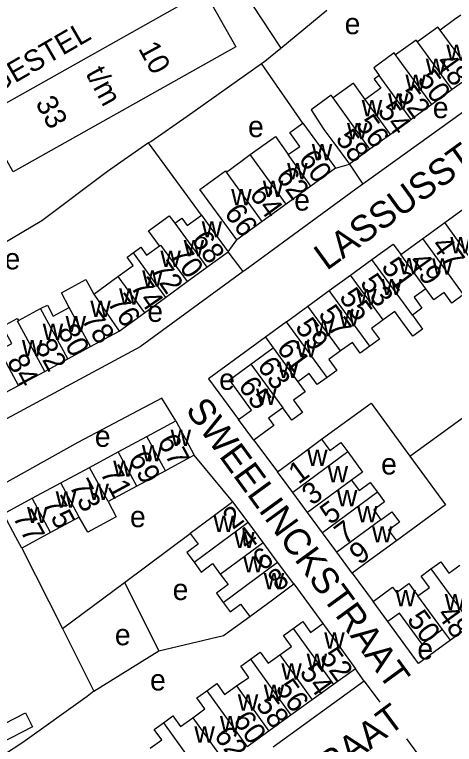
# Model space of a CAD drawing. Extents: x 159045 to 160918, y 380454 to 382516.
# Drawn here: x 159907.1 to 159990.1, y 381294.6 to 381432.4 of the extents above; entities that cross this region are included whole.
import ezdxf

# ---------------------------------------------------------------- set-up
doc = ezdxf.new("R2010")
doc.units = 0
for name, color, linetype in [('BLT_Basislijn', 7, 'Continuous'), ('BLT_Bebouwing', 7, 'Continuous'), ('BLT_Centroide', 7, 'Continuous'), ('BLT_Huisnummer', 7, 'Continuous'), ('BLT_Huisnummer_ tussenligend', 7, 'Continuous'), ('BLT_Huisnummer_zonder_bebouwing', 7, 'Continuous'), ('BLT_Onderverdeling_panden', 7, 'Continuous'), ('BLT_Plantopo', 7, 'Continuous'), ('BLT_Straatnaam', 7, 'Continuous'), ('BLT_Straatnaam_verkleind', 7, 'Continuous')]:
    doc.layers.add(name, color=color, linetype=linetype)

msp = doc.modelspace()

# ---------------------------------------------------------------- linework, layer by layer
at = {"layer": 'BLT_Basislijn'}
for p, q in [((159957.35, 381426.13), (159966.05, 381433.28)), ((159939.67, 381413.24), (159953.68, 381423.18)), ((159961.5, 381411.96), (159953.68, 381423.18)), ((160004.68, 381423.38), (159972.84, 381400.42)), ((159942.37, 381394.57), (159932.38, 381408.21)), ((159967.69, 381403.45), (159970.28, 381404.18)), ((159970.28, 381404.18), (159972.84, 381400.42)), ((159947.41, 381387.65), (159949.03, 381389.88)), ((159950.25, 381383.9), (159947.41, 381387.65)), ((159981.71, 381349.05), (160016.01, 381374.12)), ((159937.49, 381355.7), (159934.9, 381360.03)), ((159952.22, 381352.05), (159956.71, 381346.11)), ((159948.31, 381340.43), (159940.98, 381349.22)), ((159927.82, 381325.22), (159940.24, 381334.46)), ((159908.46, 381331.7), (159916.1, 381316.49)), ((159970.82, 381326.94), (159974.76, 381321.6)), ((159916.1, 381316.49), (159927.82, 381325.22)), ((159927.82, 381325.22), (159934.31, 381312.3)), ((159959.78, 381324.93), (159965.25, 381317.43)), ((159916.1, 381316.49), (159922.02, 381304.7)), ((159922.02, 381304.7), (159934.31, 381312.3)), ((159973.08, 381306.59), (159971.41, 381308.89)), ((159973.08, 381306.59), (159976.06, 381302.58)), ((159981.09, 381295.66), (159984.02, 381291.61))]:
    msp.add_line(p, q, dxfattribs=at)
for points in [[(159934.28, 381462.49), (159944.7, 381445.38), (159955.5, 381428.86), (159957.35, 381426.13)], [(159953.68, 381423.18), (159954.31, 381423.63), (159957.35, 381426.13)], [(159932.38, 381408.21), (159932.8, 381408.48), (159939.67, 381413.24)], [(159932.38, 381408.21), (159924.6, 381402.83), (159912.24, 381393.51), (159886.48, 381378.25)], [(159972.84, 381400.42), (159971.51, 381399.46), (159950.54, 381384.11), (159950.25, 381383.9)], [(159950.25, 381383.9), (159930.77, 381369.73), (159899.79, 381353.03)], [(159954.43, 381371.54), (159943.71, 381363.68), (159949.36, 381355.98)], [(159934.9, 381360.03), (159919.03, 381351.63), (159902.43, 381342.39), (159903.09, 381341.29)], [(159965.04, 381352.24), (159974.39, 381359.07), (159981.71, 381349.05)], [(159981.71, 381349.05), (159988.42, 381339.87), (159979.15, 381333.07)], [(159934.31, 381312.3), (159946.53, 381315.18), (159951.47, 381318.77)], [(159989.36, 381314.28), (159983.36, 381309.88), (159977.55, 381317.81)], [(159973.08, 381306.59), (159955.92, 381294.07)], [(159922.02, 381304.7), (159920.78, 381303.64), (159908.65, 381294.99), (159905.36, 381292.86)]]:
    msp.add_lwpolyline(points, dxfattribs=at)
at = {"layer": 'BLT_Bebouwing'}
for p, q in [((159993.59, 381421.11), (159989.7, 381418.29)), ((159989.7, 381418.29), (159985.82, 381415.46)), ((159985.82, 381415.46), (159981.93, 381412.64)), ((159981.93, 381412.64), (159978.05, 381409.82)), ((159978.05, 381409.82), (159974.16, 381407)), ((159974.16, 381407), (159970.28, 381404.18)), ((159967.69, 381403.45), (159963.02, 381400.06)), ((159963.02, 381400.06), (159958.36, 381396.67)), ((159958.36, 381396.67), (159953.85, 381393.39)), ((159988.29, 381393.15), (159992.03, 381395.88)), ((159953.85, 381393.39), (159949.03, 381389.88)), ((159984.15, 381390.14), (159988.29, 381393.15)), ((159979.99, 381387.11), (159984.15, 381390.14)), ((159943.39, 381384.72), (159947.41, 381387.65)), ((159970.5, 381383.25), (159974.52, 381386.18)), ((159939.66, 381382.01), (159943.39, 381384.72)), ((159922.04, 381379.64), (159926.6, 381382.96)), ((159966.49, 381380.33), (159970.5, 381383.25)), ((159935.58, 381379.03), (159939.66, 381382.01)), ((159962.45, 381377.38), (159966.49, 381380.33)), ((159931.58, 381376.12), (159935.58, 381379.03)), ((159958.39, 381374.42), (159962.45, 381377.38)), ((159907.79, 381374.65), (159911.99, 381376.92)), ((159926.83, 381372.66), (159931.58, 381376.12)), ((159921.42, 381369.74), (159926.83, 381372.66)), ((159917.12, 381367.42), (159921.42, 381369.74)), ((159951.69, 381366.4), (159955.92, 381369.49)), ((159912.78, 381365.07), (159917.12, 381367.42)), ((159947.64, 381363.46), (159951.69, 381366.4)), ((159907.79, 381362.37), (159912.78, 381365.07)), ((159902.82, 381359.69), (159907.79, 381362.37)), ((159932.07, 381352.78), (159937.49, 381355.7)), ((159937.49, 381355.7), (159940.98, 381349.22)), ((159926.65, 381349.86), (159932.07, 381352.78)), ((159921.23, 381346.94), (159926.65, 381349.86)), ((159915.81, 381344.02), (159921.23, 381346.94)), ((159935.56, 381346.3), (159930.14, 381343.38)), ((159959.59, 381342.19), (159956.71, 381346.11)), ((159910.39, 381341.1), (159915.81, 381344.02)), ((159930.14, 381343.38), (159924.72, 381340.46)), ((159962.38, 381338.41), (159959.59, 381342.19)), ((159904.96, 381338.18), (159910.39, 381341.1)), ((159951.16, 381336.57), (159948.31, 381340.43)), ((159919.3, 381337.54), (159913.88, 381334.62)), ((159965.18, 381334.6), (159962.38, 381338.41)), ((159953.98, 381332.76), (159951.16, 381336.57)), ((159913.88, 381334.62), (159908.46, 381331.7)), ((159967.89, 381330.91), (159965.18, 381334.6)), ((159956.74, 381329.04), (159953.98, 381332.76)), ((159970.82, 381326.94), (159967.89, 381330.91)), ((159959.78, 381324.93), (159956.74, 381329.04)), ((159974.76, 381321.6), (159978.45, 381324.29)), ((159977.55, 381317.81), (159974.76, 381321.6)), ((159967.29, 381305.92), (159963.27, 381303.02)), ((159963.27, 381303.02), (159959.25, 381300.11)), ((159959.25, 381300.11), (159955.08, 381297.1)), ((159955.08, 381297.1), (159951, 381294.16))]:
    msp.add_line(p, q, dxfattribs=at)
for points in [[(159991.35, 381432.36), (159990.15, 381431.49), (159987.42, 381429.51)], [(159987.42, 381429.51), (159986.99, 381430.09), (159983.13, 381427.29)], [(159983.13, 381427.29), (159982.88, 381427.63), (159979.01, 381424.82)], [(159979.01, 381424.82), (159978.73, 381425.21), (159974.87, 381422.4), (159975.89, 381420.96)], [(159975.89, 381420.96), (159974.96, 381420.28), (159976.23, 381418.54), (159973.27, 381416.4)], [(159973.27, 381416.4), (159971.08, 381419.5), (159967.21, 381416.7)], [(159967.21, 381416.7), (159966.84, 381417.2), (159963.06, 381414.46), (159965.49, 381410.77), (159967.34, 381408.23), (159970.28, 381404.18)], [(159958.7, 381406.01), (159960.93, 381407.52), (159959.02, 381410.16), (159961.5, 381411.96)], [(159961.5, 381411.96), (159964.75, 381407.5), (159967.69, 381403.45)], [(159951.58, 381406), (159956.31, 381409.44), (159958.7, 381406.01)], [(159947.07, 381402.71), (159951.58, 381406)], [(159949.03, 381389.88), (159946.09, 381393.92), (159942.08, 381399.43), (159946.9, 381402.94), (159947.07, 381402.71)], [(159934.45, 381388.79), (159932.39, 381391.62), (159936.29, 381394.46), (159937.33, 381393.03)], [(159937.33, 381393.03), (159938.64, 381393.98), (159939.65, 381392.59), (159942.37, 381394.57)], [(159942.37, 381394.57), (159944.47, 381391.7), (159947.41, 381387.65)], [(159929.44, 381387.45), (159930.9, 381388.51), (159932, 381387), (159934.45, 381388.79)], [(159974.52, 381386.18), (159978.54, 381389.1), (159979.99, 381387.11)], [(159926.6, 381382.96), (159929.49, 381385.06), (159928.33, 381386.64), (159929.44, 381387.45)], [(159917.41, 381377.15), (159915.92, 381379.91), (159920.54, 381382.4), (159922.04, 381379.64)], [(159984.69, 381380.65), (159982.51, 381379.06), (159983.99, 381377.03), (159982.17, 381375.7)], [(159991.85, 381379.56), (159989.64, 381377.96), (159988.17, 381379.98), (159986.22, 381378.56), (159984.69, 381380.65)], [(159911.99, 381376.92), (159913.27, 381377.6), (159914.39, 381375.52), (159917.41, 381377.15)], [(159982.17, 381375.7), (159984.1, 381373.04), (159982.28, 381371.71), (159980.34, 381374.36), (159978.87, 381376.39), (159976.67, 381374.79)], [(159904.16, 381369.08), (159906.53, 381370.36), (159904.81, 381373.54), (159907.58, 381375.04), (159907.79, 381374.65)], [(159976.67, 381374.79), (159974.47, 381373.19), (159975.96, 381371.15), (159974.15, 381369.83)], [(159958.39, 381374.42), (159954.43, 381371.54)], [(159954.43, 381371.54), (159955.92, 381369.49)], [(159974.15, 381369.83), (159972.33, 381368.5), (159970.85, 381370.54), (159968.62, 381368.92)], [(159968.62, 381368.92), (159966.39, 381367.29), (159967.89, 381365.23), (159966.06, 381363.9)], [(159966.06, 381363.9), (159964.23, 381362.56), (159962.7, 381364.67), (159960.57, 381363.11)], [(159949.36, 381355.98), (159951.8, 381357.76), (159947.64, 381363.46)], [(159960.57, 381363.11), (159961.94, 381361.22), (159959.74, 381359.62), (159961.43, 381357.31), (159959.39, 381355.83), (159957.7, 381358.15)], [(159957.7, 381358.15), (159955.02, 381356.2), (159956.02, 381354.82), (159952.22, 381352.05)], [(159952.22, 381352.05), (159949.36, 381355.98)], [(159956.71, 381346.11), (159960.74, 381349.08), (159965.04, 381352.24)], [(159965.04, 381352.24), (159966.59, 381350.14), (159968.65, 381351.66), (159969.99, 381349.84)], [(159969.99, 381349.84), (159972.77, 381346.06), (159970.67, 381344.51)], [(159940.98, 381349.22), (159936.58, 381346.85), (159935.56, 381346.3)], [(159970.67, 381344.51), (159972.12, 381342.54), (159974.21, 381344.08), (159975.57, 381342.24)], [(159975.57, 381342.24), (159976.92, 381340.41), (159974.89, 381338.91), (159976.25, 381337.06)], [(159924.72, 381340.46), (159926.27, 381337.57), (159920.91, 381334.68), (159919.3, 381337.54)], [(159948.31, 381340.43), (159944.29, 381337.46), (159940.24, 381334.46)], [(159908.46, 381331.7), (159907.34, 381333.78), (159904.96, 381338.18)], [(159976.25, 381337.06), (159978.28, 381338.55), (159979.72, 381336.6), (159977.66, 381335.08), (159979.15, 381333.07)], [(159940.24, 381334.46), (159941.72, 381332.45), (159939.59, 381330.88), (159940.96, 381329.02)], [(159979.15, 381333.07), (159974.84, 381329.9), (159970.82, 381326.94)], [(159985.68, 381327.76), (159987.52, 381329.1), (159989.08, 381326.97), (159991.12, 381328.45)], [(159940.96, 381329.02), (159942.33, 381327.17), (159944.46, 381328.76), (159945.92, 381326.79)], [(159983.21, 381322.69), (159985.39, 381324.28), (159983.84, 381326.41), (159985.68, 381327.76)], [(159945.92, 381326.79), (159947.37, 381324.83), (159945.17, 381323.2), (159946.47, 381321.44)], [(159951.47, 381318.77), (159955.76, 381321.95), (159959.78, 381324.93)], [(159978.45, 381324.29), (159979.17, 381323.3), (159981.52, 381325.02), (159983.21, 381322.69)], [(159946.47, 381321.44), (159947.78, 381319.67), (159949.73, 381321.12), (159951.47, 381318.77)], [(159987.85, 381316.34), (159984, 381313.53), (159979.72, 381319.39), (159977.55, 381317.81)], [(159959.66, 381316.5), (159961.5, 381317.82), (159962.97, 381315.78), (159965.25, 381317.43)], [(159965.25, 381317.43), (159971.41, 381308.89)], [(159993.38, 381317.21), (159989.36, 381314.28)], [(159957.15, 381311.51), (159959.33, 381313.08), (159957.82, 381315.17), (159959.66, 381316.5)], [(159989.36, 381314.28), (159987.85, 381316.34)], [(159951.61, 381310.7), (159953.46, 381312.03), (159954.97, 381309.94), (159957.15, 381311.51)], [(159949, 381305.66), (159951.28, 381307.28), (159949.77, 381309.37), (159951.61, 381310.7)], [(159971.41, 381308.89), (159967.29, 381305.92)], [(159943.36, 381304.76), (159945.23, 381306.11), (159946.72, 381304.04), (159949, 381305.66)], [(159940.7, 381299.65), (159943, 381301.31), (159941.49, 381303.41), (159943.36, 381304.76)], [(159905.14, 381298.48), (159909.11, 381300.56), (159910.46, 381297.96), (159904.37, 381294.78), (159905.36, 381292.86)], [(159932.68, 381293.91), (159934.86, 381295.48), (159933.43, 381297.45), (159935.2, 381298.72)], [(159935.2, 381298.72), (159936.96, 381299.99), (159938.4, 381297.99), (159940.7, 381299.65)]]:
    msp.add_lwpolyline(points, dxfattribs=at)
at = {"layer": 'BLT_Onderverdeling_panden'}
for p, q in [((159993.59, 381421.11), (159987.42, 381429.51)), ((159989.7, 381418.29), (159983.13, 381427.29)), ((159985.82, 381415.46), (159979.01, 381424.82)), ((159981.93, 381412.64), (159975.89, 381420.96)), ((159974.16, 381407), (159967.21, 381416.7)), ((159978.05, 381409.82), (159973.27, 381416.4)), ((159958.36, 381396.67), (159951.58, 381406)), ((159963.02, 381400.06), (159958.7, 381406.01)), ((159953.85, 381393.39), (159947.07, 381402.71)), ((159937.33, 381393.03), (159943.39, 381384.72)), ((159992.8, 381386.96), (159988.29, 381393.15)), ((159991.85, 381379.56), (159984.15, 381390.14)), ((159929.44, 381387.45), (159935.58, 381379.03)), ((159984.69, 381380.65), (159979.99, 381387.11)), ((159982.17, 381375.7), (159974.52, 381386.18)), ((159926.6, 381382.96), (159931.58, 381376.12)), ((159976.67, 381374.79), (159970.5, 381383.25)), ((159974.15, 381369.83), (159966.49, 381380.33)), ((159922.04, 381379.64), (159926.83, 381372.66)), ((159968.62, 381368.92), (159962.45, 381377.38)), ((159917.12, 381367.42), (159911.99, 381376.92)), ((159921.42, 381369.74), (159917.41, 381377.15)), ((159966.06, 381363.9), (159958.39, 381374.42)), ((159907.79, 381362.37), (159904.16, 381369.08)), ((159955.92, 381369.49), (159960.57, 381363.11)), ((159951.69, 381366.4), (159957.7, 381358.15)), ((159935.56, 381346.3), (159932.07, 381352.78)), ((159930.14, 381343.38), (159926.65, 381349.86)), ((159969.99, 381349.84), (159959.59, 381342.19)), ((159924.72, 381340.46), (159921.23, 381346.94)), ((159970.67, 381344.51), (159962.38, 381338.41)), ((159919.3, 381337.54), (159915.81, 381344.02)), ((159975.57, 381342.24), (159965.18, 381334.6)), ((159913.88, 381334.62), (159910.39, 381341.1)), ((159940.96, 381329.02), (159951.16, 381336.57)), ((159976.25, 381337.06), (159967.89, 381330.91)), ((159945.92, 381326.79), (159953.98, 381332.76)), ((159946.47, 381321.44), (159956.74, 381329.04)), ((159985.68, 381327.76), (159993.38, 381317.21)), ((159987.85, 381316.34), (159983.21, 381322.69)), ((159959.66, 381316.5), (159967.29, 381305.92)), ((159957.15, 381311.51), (159963.27, 381303.02)), ((159951.61, 381310.7), (159959.25, 381300.11)), ((159949, 381305.66), (159955.08, 381297.1)), ((159943.36, 381304.76), (159951, 381294.16)), ((159935.2, 381298.72), (159942.77, 381288.22)), ((159940.7, 381299.65), (159946.83, 381291.15))]:
    msp.add_line(p, q, dxfattribs=at)
for points in [[(159934.45, 381388.79), (159934.63, 381388.91), (159939.66, 381382.01)], [(159912.78, 381365.07), (159907.65, 381374.57), (159907.79, 381374.65)]]:
    msp.add_lwpolyline(points, dxfattribs=at)
at = {"layer": 'BLT_Plantopo'}
msp.add_lwpolyline([(159900.91, 381413.18), (159942.93, 381436.84), (159948.82, 381426.38), (159906.8, 381402.72)], close=True, dxfattribs=at)

# ---------------------------------------------------------------- texts
at = {"layer": 'BLT_Centroide'}
for s, p in [('e', (159969.39, 381428.74)), ('w', (159988.59, 381423.72)), ('w', (159984.7, 381421.08)), ('w', (159980.86, 381418.05)), ('w', (159977.59, 381414.52)), ('w', (159972.62, 381413.22)), ('e', (159986.03, 381412.88)), ('e', (159951.15, 381409.31)), ('w', (159969.83, 381408.91)), ('w', (159963.19, 381404.91)), ('w', (159958.53, 381401.33)), ('w', (159953.94, 381398)), ('w', (159947.97, 381396.41)), ('e', (159959.87, 381395.43)), ('w', (159942.39, 381390.36)), ('w', (159939, 381386.81)), ('w', (159989.34, 381387.36)), ('e', (159905.18, 381384.33)), ('w', (159934.61, 381384.78)), ('w', (159979.61, 381383.42)), ('w', (159985.92, 381383.33)), ('w', (159931.17, 381381.06)), ('w', (159976.33, 381379.47)), ('w', (159926.81, 381377.67)), ('w', (159971.58, 381377.56)), ('w', (159921.38, 381375.33)), ('e', (159932.13, 381374.41)), ('w', (159968.3, 381373.59)), ('w', (159916.7, 381372.48)), ('w', (159963.5, 381371.67)), ('w', (159912.39, 381371)), ('w', (159908.47, 381367.89)), ('w', (159960.25, 381367.72)), ('w', (159956.81, 381363.81)), ('e', (159945.7, 381361.58)), ('w', (159952.67, 381358.72)), ('e', (159922.22, 381350.81)), ('w', (159936.53, 381351)), ('w', (159931.11, 381348.08)), ('w', (159962.31, 381347.22)), ('e', (159976.27, 381345.6)), ('w', (159925.69, 381345.16)), ('w', (159966.18, 381344.12)), ('w', (159921.03, 381340.8)), ('w', (159914.84, 381339.31)), ('w', (159967.92, 381339.56)), ('w', (159909.42, 381336.41)), ('e', (159928.86, 381335.64)), ('w', (159971.73, 381336.56)), ('w', (159944.64, 381334.72)), ('w', (159948.54, 381331.69)), ('w', (159974.55, 381332.75)), ('w', (159950.23, 381327.09)), ('w', (159954.11, 381323.91)), ('e', (159936.92, 381321.88)), ('w', (159978.98, 381320.7)), ('w', (159988.3, 381319.95)), ('e', (159926.01, 381313.34)), ('w', (159965.53, 381312.69)), ('e', (159983.12, 381310.66)), ('w', (159962.22, 381308.7)), ('w', (159957.44, 381306.86)), ('e', (159932.65, 381304.8)), ('w', (159954.12, 381302.83)), ('w', (159949.22, 381300.98)), ('w', (159945.84, 381296.91)), ('w', (159941.02, 381294.94))]:
    msp.add_text(s, height=4, dxfattribs=at).set_placement(p)
at = {"layer": 'BLT_Huisnummer'}
for s, rotation, p in [('48', 305.9836, (159986.49, 381423.41)), ('52', 305.9869, (159979.14, 381417.28)), ('56', 305.976, (159971.37, 381411.74)), ('60', 306.0331, (159960.54, 381405.12)), ('64', 306.0323, (159951.28, 381398.47)), ('68', 306.0658, (159940.29, 381389.85)), ('47', 306.0741, (159985.62, 381388.86)), ('72', 304.5106, (159932.52, 381384.26)), ('51', 306.0819, (159976.17, 381384.77)), ('76', 304.5106, (159924.45, 381377.99)), ('55', 306.0779, (159968.21, 381379.04)), ('59', 306.0781, (159959.9, 381373.39)), ('80', 298.3766, (159915.08, 381372.7)), ('84', 298.3741, (159905.53, 381367)), ('65', 306.0752, (159949.16, 381362.3)), ('67', 298.3081, (159933.96, 381351.93)), ('71', 298.3081, (159923.14, 381345.92)), ('1', 36.3479, (159960.67, 381343.64)), ('5', 36.3572, (159966.63, 381335.98)), ('77', 298.3132, (159906.65, 381337.57)), ('2', 36.506, (159948.3, 381335.08)), ('9', 36.3475, (159972.16, 381328.4)), ('8', 36.5077, (159956.82, 381323.35)), ('50', 306.1388, (159981.01, 381318.17)), ('52', 305.7874, (159964.5, 381311.08)), ('56', 305.7902, (159956.19, 381305.19)), ('60', 305.797, (159948.16, 381299.15))]:
    msp.add_text(s, height=4, rotation=rotation, dxfattribs=at).set_placement(p)
at = {"layer": 'BLT_Huisnummer_ tussenligend'}
for s, rotation, p in [('50', 305.9836, (159982.95, 381420.19)), ('54', 305.9869, (159975.45, 381414.22)), ('58', 305.976, (159967.54, 381408.97)), ('62', 306.0331, (159956.25, 381401.89)), ('66', 306.0323, (159946.52, 381394.93)), ('70', 306.0658, (159936.3, 381387.1)), ('49', 306.0741, (159981.37, 381385.78)), ('74', 304.5106, (159928.83, 381381.05)), ('53', 306.0819, (159972.15, 381381.72)), ('57', 306.0779, (159964.28, 381375.81)), ('78', 304.5106, (159919.55, 381374.77)), ('82', 298.3766, (159910.79, 381369.92)), ('61', 306.0781, (159956.41, 381369.44)), ('63', 306.0781, (159952.74, 381366.05)), ('69', 298.3081, (159928.51, 381348.69)), ('73', 298.3081, (159917.3, 381343.42)), ('3', 36.3479, (159963.2, 381339.62)), ('75', 298.3081, (159912.35, 381340.18)), ('7', 36.3572, (159969.35, 381332.22)), ('4', 36.506, (159951.01, 381331.15)), ('6', 36.506, (159953.91, 381327.22)), ('48', 306.1316, (159986.68, 381319.11)), ('54', 305.7874, (159960.74, 381308.19)), ('58', 305.7902, (159952.45, 381302.11)), ('62', 305.797, (159944.59, 381296.24))]:
    msp.add_text(s, height=4, rotation=rotation, dxfattribs=at).set_placement(p)
at = {"layer": 'BLT_Huisnummer_zonder_bebouwing'}
for s, p in [('10', (159930.35, 381426.05)), ('t/m', (159920.39, 381421.34)), ('33', (159910.92, 381415.74))]:
    msp.add_text(s, height=4, rotation=298.645, dxfattribs=at).set_placement(p)
at = {"layer": 'BLT_Straatnaam'}
for s, rotation, p in [('LASSUSSTRAAT', 35.9358, (159966, 381383.99)), ('SWEELINCKSTRAAT', 306.1031, (159939.21, 381357.77)), ('ARCADELTSTRAAT', 36.5844, (159931.21, 381261.64))]:
    msp.add_text(s, height=5, rotation=rotation, dxfattribs=at).set_placement(p)
at = {"layer": 'BLT_Straatnaam_verkleind'}
msp.add_text('HOF VAN GESTEL', height=4, rotation=30.059, dxfattribs=at).set_placement((159881.67, 381404.71))

doc.saveas('drawing.dxf')
